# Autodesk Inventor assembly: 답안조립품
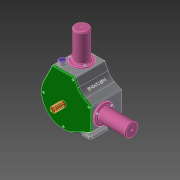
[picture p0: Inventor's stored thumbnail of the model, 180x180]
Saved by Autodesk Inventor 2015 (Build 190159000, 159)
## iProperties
Created: 2022-01
Part Number: 답안조립품
Document SubType Name: Assembly
Designer: user
Author: user
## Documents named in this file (13)
- C:\Users\user\Desktop\620117V1007\답안조립품.iam
- C:\Users\user\Desktop\620117V1007\너트 M3.ipt
- C:\Users\user\Desktop\620117V1007\베어링 20 x 37 x 9.ipt
- C:\Users\user\Desktop\620117V1007\본체.ipt
- C:\Users\user\Desktop\620117V1007\볼트 M3 x 12.ipt
- C:\Users\user\Desktop\620117V1007\실린더.ipt
- C:\Users\user\Desktop\620117V1007\앞커버.ipt
- C:\Users\user\Desktop\620117V1007\축.ipt
- C:\Users\user\Desktop\620117V1007\측정게이지.ipt
- C:\Users\user\Desktop\620117V1007\커넥팅로드 캡.ipt
- C:\Users\user\Desktop\620117V1007\커넥팅로드.ipt
- C:\Users\user\Desktop\620117V1007\피스톤 핀.ipt
- C:\Users\user\Desktop\620117V1007\피스톤.ipt
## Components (4 placed, 2 different names)
1. 피스톤 핀:1
2. 피스톤:1
3. 피스톤:2
4. 피스톤 핀:2
